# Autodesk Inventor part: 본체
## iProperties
Created: 2014-12
Part Number: 본체
Document SubType Name: Modeling
Designer: tw009
Density: 2.71 g/cm^3
Material: 알루미늄-6061
Mass: 606.943 g
Surface Area: 658.73 cm^2
Volume: 223.964 cm^3
Author: tw009
